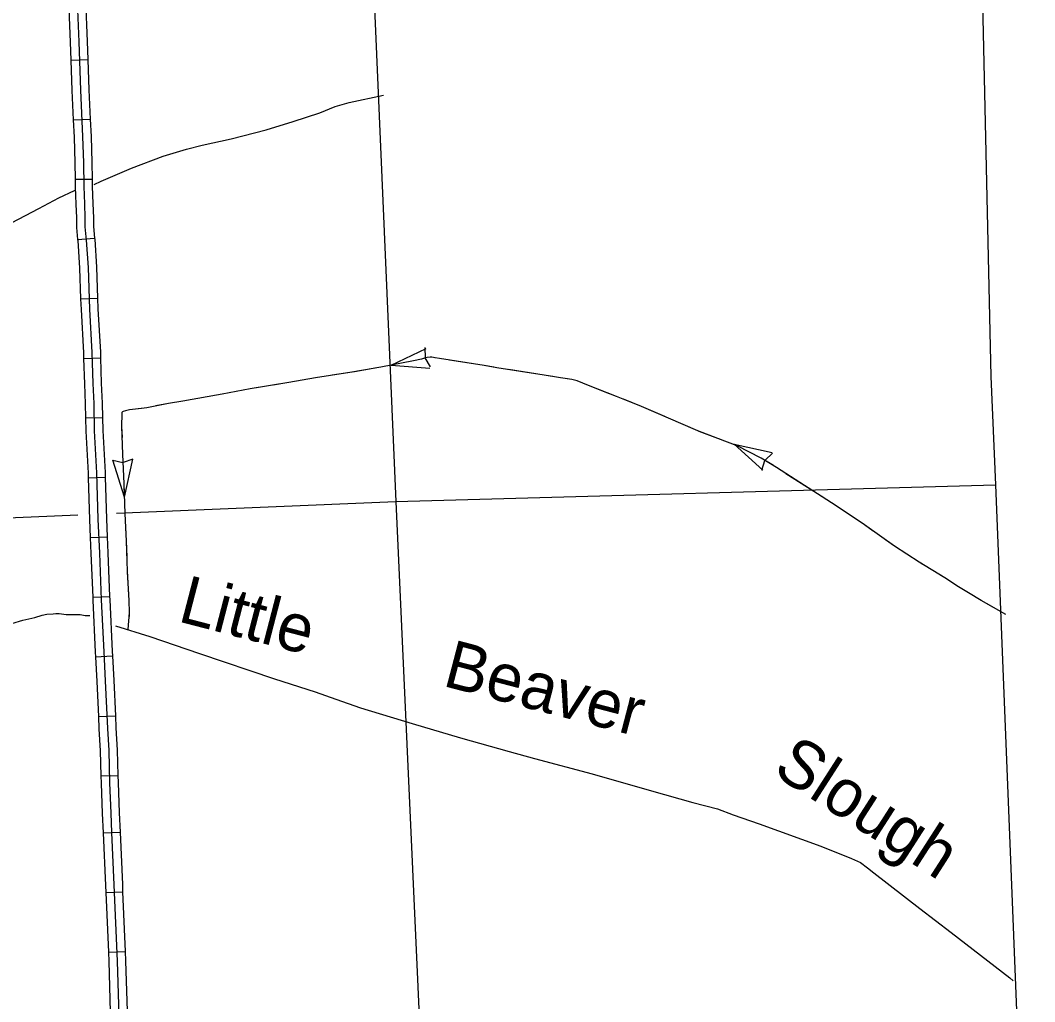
# Model space of a CAD drawing. Extents: x 1720274 to 1751788, y 372074 to 391887.
# Drawn here: x 1739571 to 1740989, y 379057 to 380428 of the extents above; entities that cross this region are included whole.
import ezdxf

# ---------------------------------------------------------------- set-up
doc = ezdxf.new("R2010")
doc.units = 0
for name, color, linetype in [('Level 2', 7, 'Continuous'), ('Level 32', 7, 'Continuous'), ('Level 35', 7, 'Continuous'), ('Level 43', 7, 'Continuous'), ('Level 5', 7, 'Continuous')]:
    doc.layers.add(name, color=color, linetype=linetype)

msp = doc.modelspace()

# ---------------------------------------------------------------- linework, layer by layer
at = {"layer": 'Level 2'}
msp.add_lwpolyline([(1740910.8, 380618.1), (1740915, 380494), (1740927.6, 379930.4), (1740933.9, 379779.1), (1740967.4, 378940), (1740967.5, 378934.1), (1740976, 378812.1), (1740987.9, 378633.8), (1740988.7, 378613.3)], dxfattribs=at)
at = {"layer": 'Level 32'}
for p, q in [((1739642, 380372.4), (1739665.7, 380373.2)), ((1739645.4, 380288.9), (1739669.1, 380290)), ((1739648.1, 380205.9), (1739671.8, 380206.3)), ((1739651.5, 380121.6), (1739675.1, 380123.9)), ((1739655.7, 380039), (1739679.4, 380039.9)), ((1739659.8, 379955.8), (1739683.5, 379956.5)), ((1739662.5, 379872.6), (1739686.2, 379873)), ((1739666.3, 379789.1), (1739690, 379789.8)), ((1739669.1, 379705.6), (1739692.8, 379706.6)), ((1739672.5, 379622.2), (1739696.2, 379623.2)), ((1739676.5, 379538.7), (1739700.1, 379540)), ((1739680.5, 379455.5), (1739704.2, 379456.6)), ((1739683.9, 379372.4), (1739707.6, 379373)), ((1739687.1, 379293), (1739710.8, 379294)), ((1739690.8, 379209.6), (1739714.4, 379210.6)), ((1739694.4, 379126.3), (1739718, 379127.3))]:
    msp.add_line(p, q, dxfattribs=at)
for points in [[(1739649.7, 380476.6), (1739653, 380397.9), (1739655.3, 380330.6), (1739658.4, 380265.5), (1739659.5, 380229), (1739660.1, 380195.8), (1739661.1, 380171.7), (1739661.7, 380152), (1739661.7, 380139.4), (1739663.5, 380121.1), (1739666.1, 380082.6), (1739668.1, 380024.5), (1739671.5, 379963.9), (1739672.7, 379920.7), (1739674, 379892.6), (1739674.7, 379854.4), (1739678, 379796), (1739679.9, 379731.2), (1739681.9, 379683.8), (1739684.5, 379618.4), (1739687.9, 379545.8), (1739690.1, 379505.1), (1739693.1, 379438.9), (1739694.9, 379408), (1739696, 379362.8), (1739697.7, 379320.6), (1739699, 379293.5)], [(1739638.7, 380455.6), (1739641.1, 380397.5), (1739642, 380372.4)], [(1739662.4, 380456.7), (1739664.8, 380398.4), (1739665.7, 380373.2)], [(1739642, 380372.4), (1739643.4, 380330.1), (1739645.4, 380288.9)], [(1739665.7, 380373.2), (1739667.1, 380331.1), (1739669.1, 380290)], [(1739669.1, 380290), (1739670.3, 380265.9), (1739671.4, 380229.3), (1739671.8, 380206.3)], [(1739645.4, 380288.9), (1739646.6, 380265), (1739647.7, 380228.7), (1739648.1, 380205.9)], [(1739648.1, 380205.9), (1739648.2, 380195.4), (1739649.2, 380171.3), (1739649.8, 380151.9), (1739649.8, 380138.8), (1739651.5, 380121.6)], [(1739671.8, 380206.3), (1739671.9, 380196.1), (1739672.9, 380172.1), (1739673.5, 380152.2), (1739673.5, 380140), (1739675.1, 380123.9)], [(1739651.5, 380121.6), (1739651.7, 380120.2), (1739654.3, 380082), (1739655.7, 380039)], [(1739675.1, 380123.9), (1739675.3, 380122.1), (1739677.9, 380083.2), (1739679.4, 380039.9)], [(1739655.7, 380039), (1739656.3, 380023.9), (1739659.6, 379963.4), (1739659.8, 379955.8)], [(1739679.4, 380039.9), (1739679.9, 380025), (1739683.3, 379964.4), (1739683.5, 379956.5)], [(1739659.8, 379955.8), (1739660.9, 379920.3), (1739662.2, 379892.2), (1739662.5, 379872.6)], [(1739683.5, 379956.5), (1739684.5, 379921.2), (1739685.9, 379893), (1739686.2, 379873)], [(1739662.5, 379872.6), (1739662.9, 379853.9), (1739666.2, 379795.5), (1739666.3, 379789.1)], [(1739686.2, 379873), (1739686.6, 379854.8), (1739689.8, 379796.5), (1739690, 379789.8)], [(1739666.3, 379789.1), (1739668.1, 379730.8), (1739669.1, 379705.6)], [(1739690, 379789.8), (1739691.8, 379731.6), (1739692.8, 379706.6)], [(1739669.1, 379705.6), (1739670.1, 379683.4), (1739672.5, 379622.2)], [(1739692.8, 379706.6), (1739693.8, 379684.3), (1739696.2, 379623.2)], [(1739672.5, 379622.2), (1739672.7, 379617.9), (1739676.1, 379545.2), (1739676.5, 379538.7)], [(1739696.2, 379623.2), (1739696.4, 379619), (1739699.8, 379546.4), (1739700.1, 379540)], [(1739676.5, 379538.7), (1739678.3, 379504.5), (1739680.5, 379455.5)], [(1739700.1, 379540), (1739702, 379505.7), (1739704.2, 379456.6)], [(1739680.5, 379455.5), (1739681.3, 379438.3), (1739683, 379407.5), (1739683.9, 379372.4)], [(1739704.2, 379456.6), (1739705, 379439.5), (1739706.7, 379408.4), (1739707.6, 379373)], [(1739683.9, 379372.4), (1739684.2, 379362.4), (1739685.9, 379320.1), (1739687.1, 379292.9)], [(1739707.6, 379373), (1739707.9, 379363.2), (1739709.6, 379321.1), (1739710.8, 379294)], [(1739687.1, 379293), (1739690.3, 379219.5), (1739690.8, 379209.6)], [(1739699, 379293.5), (1739702.2, 379220.1), (1739706.8, 379113.7), (1739710.5, 378992.2), (1739712.8, 378916.2), (1739715.4, 378866.5), (1739718.6, 378812.5), (1739720, 378771.4), (1739721.2, 378746), (1739722.7, 378725.3), (1739723.9, 378709.2), (1739725.6, 378694.2), (1739727.2, 378679.7), (1739729.3, 378662.9), (1739730.1, 378651.9), (1739730.5, 378643.4), (1739730, 378627.9), (1739730.1, 378619.6), (1739730.3, 378618.5), (1739730.8, 378615.5)], [(1739710.8, 379294), (1739714, 379220.6), (1739714.4, 379210.6)], [(1739690.8, 379209.6), (1739694.4, 379126.3)], [(1739714.4, 379210.6), (1739718, 379127.3)], [(1739718, 379127.3), (1739718.6, 379114.2), (1739720.8, 379043.8)], [(1739694.4, 379126.3), (1739694.9, 379113.3), (1739697.1, 379043)]]:
    msp.add_lwpolyline(points, dxfattribs=at)
at = {"layer": 'Level 35'}
for points in [[(1739674.5, 380198.7), (1739684.2, 380203.4), (1739726.8, 380221.5), (1739771.1, 380238.2), (1739803.6, 380247.8), (1739825.5, 380253.5), (1739865.9, 380262.3), (1739915.1, 380275.1), (1739952.8, 380286.9), (1739990.1, 380298.8), (1740011.2, 380307.6), (1740031, 380313.3), (1740078.8, 380323.4)], [(1739423.2, 380066.5), (1739458.1, 380085.7), (1739510.8, 380115.1), (1739550.3, 380140.6), (1739597.3, 380165.2), (1739625.4, 380180.2), (1739646.9, 380190.3), (1739647.9, 380190.4)], [(1739544.2, 379580.8), (1739574.8, 379590.1), (1739591.9, 379593.6), (1739601.8, 379596.9), (1739608.4, 379598.2), (1739617.5, 379598.7), (1739621, 379599.5), (1739625.8, 379599.4), (1739635.3, 379598), (1739643.7, 379597.9), (1739648.3, 379598), (1739655, 379597.9), (1739661.9, 379596.7), (1739668.7, 379596.5)], [(1739704.6, 379582.2), (1739752.5, 379567.1), (1739821.6, 379543.5), (1739926.7, 379508.1), (1739983.4, 379490), (1740012.1, 379479.5), (1740046.5, 379467.7), (1740119.1, 379445.7), (1740186.3, 379425.6), (1740254.2, 379406.4), (1740289.9, 379396.6), (1740370.4, 379375.5), (1740453.3, 379351.6), (1740511.2, 379335.4), (1740545.3, 379326.7), (1740567.3, 379318.1), (1740603.6, 379305.4), (1740689.9, 379274.5), (1740732.6, 379257.2), (1740745.3, 379251.5), (1740755.2, 379243.9), (1740763.8, 379237.2), (1740828.2, 379187.4), (1740872.1, 379153.9), (1740902.7, 379130), (1740954, 379090.5), (1740958.7, 379086)]]:
    msp.add_lwpolyline(points, dxfattribs=at)
at = {"layer": 'Level 43'}
for p, q in [((1740089.4, 379946.2), (1740138.3, 379969.6)), ((1740136.6, 379970.9), (1740136.9, 379956.5)), ((1740144.4, 379943.9), (1740137, 379956.3)), ((1740089.4, 379946.2), (1740143.5, 379942)), ((1740568.8, 379835.9), (1740609, 379799.5)), ((1740568.8, 379835.9), (1740621.8, 379824.5)), ((1740622.4, 379823.2), (1740611.9, 379813.4)), ((1739716.9, 379761.9), (1739700.7, 379813.7)), ((1739700.7, 379813.7), (1739714.8, 379810.5)), ((1739728.8, 379814.8), (1739715, 379810.5)), ((1739716.9, 379761.9), (1739728.8, 379814.8)), ((1740607.6, 379799.4), (1740611.8, 379813.2))]:
    msp.add_line(p, q, dxfattribs=at)
for points in [[(1740948.5, 379598), (1740913.8, 379617.6), (1740896.4, 379628.3), (1740882.2, 379636.8), (1740863.2, 379649.2), (1740827.4, 379671.1), (1740793, 379693.3), (1740750.9, 379723.1), (1740711.4, 379749.6), (1740628, 379803.3), (1740606.6, 379816.5), (1740573.2, 379833.6), (1740546.2, 379843.9), (1740517.9, 379854.5), (1740439.1, 379888.6), (1740404.2, 379902.7), (1740365.3, 379917.9), (1740349.4, 379924.4), (1740341.9, 379926.4), (1740326.2, 379928.7), (1740303.3, 379932.5), (1740237.1, 379942.5), (1740219.3, 379945.8), (1740157, 379955.4), (1740150.9, 379956.4), (1740146.6, 379957.5), (1740144.2, 379957.5), (1740139.8, 379957.2), (1740136.2, 379956.2), (1740131.8, 379954.5), (1740120.9, 379952.1), (1740075.1, 379943.4), (1740064.2, 379941.8), (1740031.9, 379936), (1739983.9, 379928.8), (1739946.5, 379922.2), (1739892.5, 379913), (1739853.3, 379905.6), (1739811.3, 379898.3), (1739798.6, 379895.8), (1739778.3, 379892.7), (1739748.2, 379886.9), (1739740.7, 379885.8), (1739724.1, 379884), (1739718.4, 379882.5), (1739715.1, 379881.6), (1739714, 379880.9), (1739713.4, 379880), (1739713.1, 379878.7), (1739713, 379860.6), (1739714.4, 379822), (1739716.1, 379780.3), (1739717.5, 379739), (1739719.5, 379700.5), (1739720.9, 379658.4), (1739723.1, 379617.4), (1739723.7, 379600.9), (1739721.8, 379576.8)], [(1740150.6, 379956.5), (1740146.6, 379957.5), (1740144.2, 379957.5), (1740139.8, 379957.2), (1740136.2, 379956.2), (1740131.8, 379954.5), (1740120.9, 379952.1), (1740089.4, 379946.2)], [(1740233, 379943.3), (1740219.3, 379945.8), (1740171.2, 379953.2)], [(1740038.1, 379937.1), (1740031.9, 379936), (1740007.2, 379932.3)], [(1740068.9, 379942.5), (1740064.2, 379941.8), (1740038.1, 379937.1)], [(1740315.4, 379930.5), (1740303.3, 379932.5), (1740253.6, 379940)], [(1739986.6, 379929.2), (1739983.9, 379928.8), (1739946.5, 379922.2), (1739924.9, 379918.5)], [(1740394.8, 379906.3), (1740365.3, 379917.9), (1740349.4, 379924.4), (1740341.9, 379926.4), (1740336, 379927.3)], [(1739904.4, 379915), (1739892.5, 379913), (1739853.3, 379905.6), (1739842.8, 379903.8)], [(1739822.3, 379900.2), (1739811.3, 379898.3), (1739798.6, 379895.8), (1739778.3, 379892.7), (1739760.7, 379889.3)], [(1740471.9, 379874.4), (1740439.1, 379888.6), (1740414.2, 379898.6)], [(1739740.1, 379885.7), (1739724.1, 379884), (1739718.4, 379882.5), (1739715.1, 379881.6), (1739714, 379880.9), (1739713.4, 379880), (1739713.1, 379878.7), (1739713, 379860.6), (1739713.6, 379845.3)], [(1740519.8, 379853.8), (1740517.9, 379854.5), (1740491, 379866.1)], [(1740549, 379842.8), (1740546.2, 379843.9), (1740519.8, 379853.8)], [(1739714.3, 379824.5), (1739714.4, 379822), (1739716.1, 379780.3), (1739716.7, 379761.9)], [(1740623.7, 379805.9), (1740606.6, 379816.5), (1740573.2, 379833.6), (1740568.5, 379835.4)], [(1740693.9, 379760.9), (1740641.2, 379794.7)], [(1739717.5, 379741.1), (1739717.5, 379739), (1739719, 379709.9)], [(1740763.1, 379714.4), (1740750.9, 379723.1), (1740711.4, 379749.6)], [(1739719, 379709.9), (1739719.5, 379700.5), (1739720.2, 379678.6)], [(1740832.4, 379668), (1740827.4, 379671.1), (1740793, 379693.3), (1740780.2, 379702.4)], [(1739720.9, 379657.7), (1739723.1, 379617.4), (1739723.7, 379600.9), (1739723.3, 379595.3)], [(1740903.3, 379624.1), (1740896.4, 379628.3), (1740882.2, 379636.8), (1740863.2, 379649.2), (1740850.2, 379657.1)], [(1740948.5, 379598), (1740921.2, 379613.4)]]:
    msp.add_lwpolyline(points, dxfattribs=at)
at = {"layer": 'Level 5'}
for points in [[(1740060.2, 380585.8), (1740096, 379756)], [(1740096, 379756), (1740933.9, 379779.1)], [(1739705.8, 379739.4), (1740096, 379756)], [(1740096, 379756), (1740134.8, 378903.1)], [(1739259.5, 379720.3), (1739651.6, 379737)]]:
    msp.add_lwpolyline(points, dxfattribs=at)

# ---------------------------------------------------------------- texts
at = {"layer": 'Level 35'}
for s, rotation, p in [('Little', 345.4392, (1739789.8, 379588.8)), ('Beaver', 345.358, (1740159.8, 379498.7)), ('Slough', 327.2742, (1740620.8, 379376.1))]:
    msp.add_text(s, height=66.74, rotation=rotation, dxfattribs=at).set_placement(p)

doc.saveas('drawing.dxf')
